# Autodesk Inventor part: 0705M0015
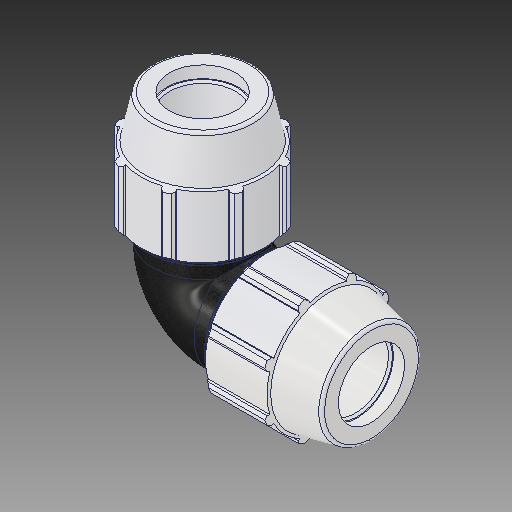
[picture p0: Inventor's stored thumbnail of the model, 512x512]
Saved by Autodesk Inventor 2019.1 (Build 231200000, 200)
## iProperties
Created: 2017-02
Part Number: 0705M0015
Material: PVC-Piping
Description: PLASSON 90° ELBOW 1 1/2'' - 1 1/2''
Document SubType Name: Modeling
Designer: KIM
Mass: 92.6774 g
Surface Area: 199.44 cm^2
Volume: 66.1981 cm^3
Density: 1.4 g/cm^3
Appearance: PTFE
Author: KIM
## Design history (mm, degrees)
derived "0705M0.ipt"
feature "Solid1::0705M0.ipt"
tag "TaggingFeature1"
body "Solid1"
other parameters: "d2" = 48.1, "d4" = 10.24467, "d5" = 30.734, "d7" = 96.012, "d9" = 17.56229, "d11" = 3.0734, "d13" = 120 deg, "d14" = 72.15, "d15" = 12 deg, "d16" = 83.53044, "d18" = 2.405, "d19" = 35 deg, "d20" = 17.5 deg, "d21" = 89.29116, "d23" = 0, "d25" = 360 deg, "d27" = 1.92024, "d33" = 0.962, "d42" = 45.48632, "d43" = 2.88036, "d46" = 1.443, "d51" = 122.936, "d59" = 90 deg, "d63" = 92.964, "d64" = 43.29, "d67" = 72.009, "d68" = 1.5367, "d70" = 90 deg, "d_" = 48.1, "E_" = 96.012, "A_" = 122.936, "l_" = 92.964
